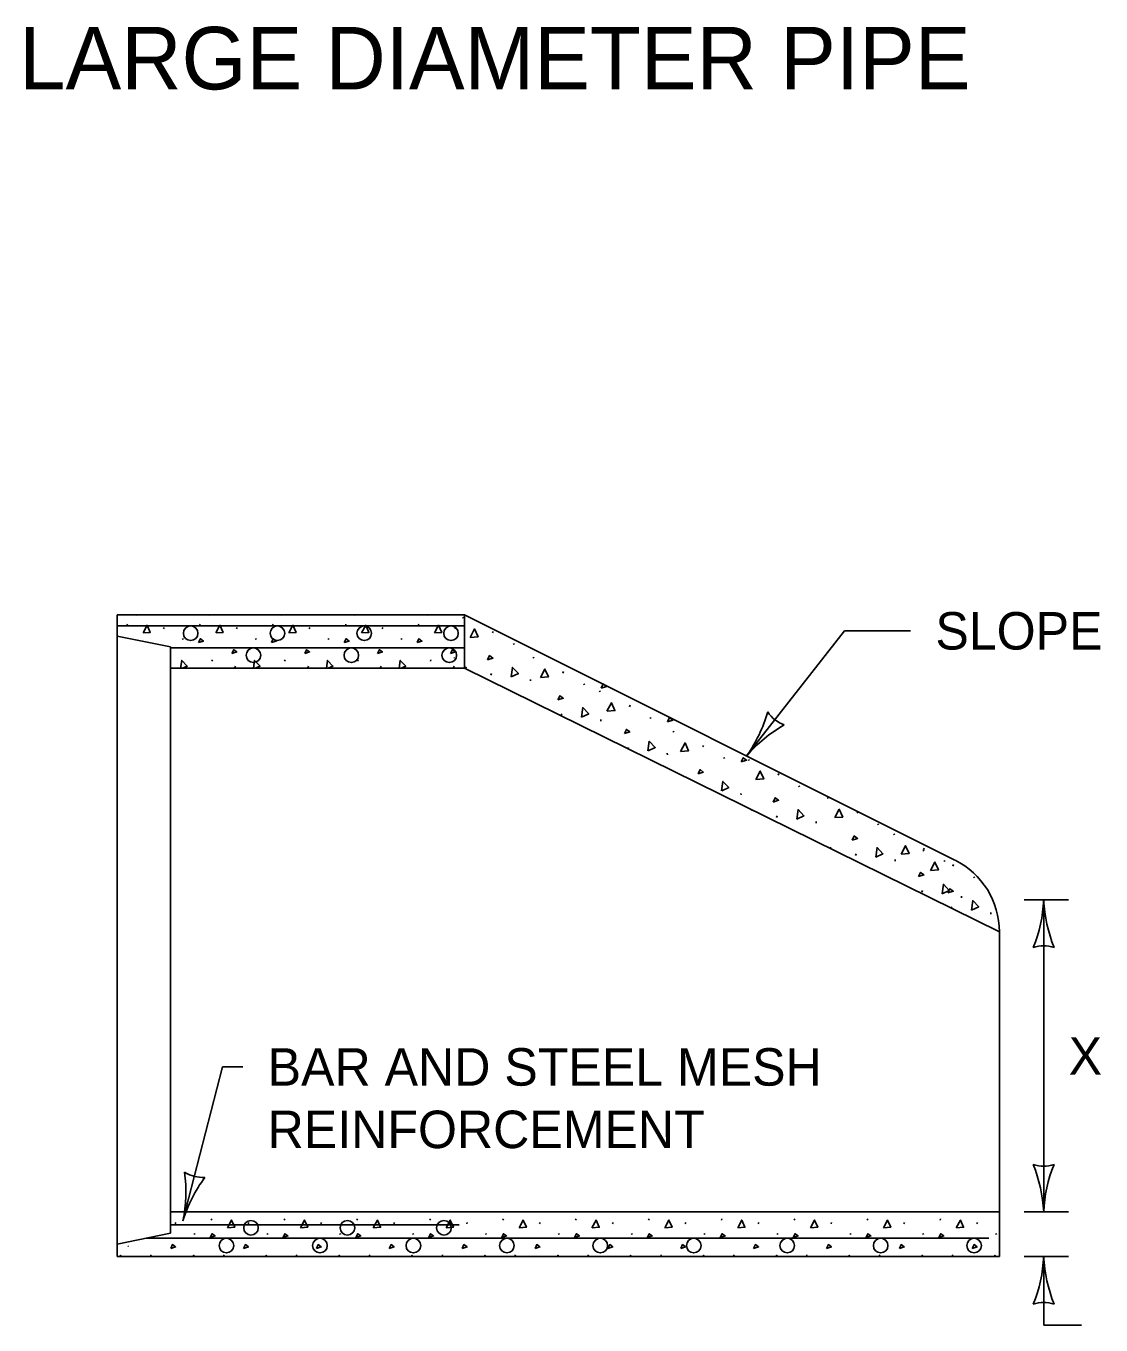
# Model space of a CAD drawing. Extents: x 49991.4 to 50022.1, y 49985 to 50011.4.
# Drawn here: x 50002.773 to 50004.494, y 49990.143 to 49992.222 of the extents above; entities that cross this region are included whole.
import ezdxf

# ---------------------------------------------------------------- set-up
doc = ezdxf.new("R2010")
doc.units = 0
for name, color, linetype in [('Level 1', 7, 'Continuous'), ('Level 2', 7, 'Continuous'), ('Level 3', 7, 'Continuous')]:
    doc.layers.add(name, color=color, linetype=linetype)

msp = doc.modelspace()

# ---------------------------------------------------------------- linework, layer by layer
at = {"layer": 'Level 1'}
for p, q in [((50002.9188, 49991.2797), (50003.4753, 49991.2797)), ((50002.9188, 49990.2549), (50002.9188, 49991.2797)), ((50002.9188, 49991.2797), (50002.9188, 49990.2723)), ((50002.9188, 49991.2797), (50003.4753, 49991.2797)), ((50002.9188, 49991.2797), (50002.9188, 49990.2549)), ((50002.9188, 49990.2549), (50002.9188, 49991.2797)), ((50002.9188, 49990.2549), (50002.9188, 49991.2797)), ((50002.9188, 49990.2549), (50002.9188, 49991.2797)), ((50002.9493, 49991.2797), (50002.9495, 49991.2793)), ((50002.9499, 49991.2797), (50002.9505, 49991.2788)), ((50003.0659, 49991.2797), (50003.0662, 49991.2793)), ((50003.0666, 49991.2797), (50003.0672, 49991.2788)), ((50003.1826, 49991.2797), (50003.1829, 49991.2793)), ((50003.1833, 49991.2797), (50003.1839, 49991.2788)), ((50003.2993, 49991.2797), (50003.2996, 49991.2793)), ((50003.3, 49991.2797), (50003.3006, 49991.2788)), ((50003.416, 49991.2797), (50003.4163, 49991.2793)), ((50003.4167, 49991.2797), (50003.4173, 49991.2788)), ((50003.4723, 49991.276), (50003.4734, 49991.2744)), ((50003.4753, 49991.2797), (50004.2605, 49990.8871)), ((50003.4753, 49991.2797), (50003.4753, 49991.1941)), ((50003.4753, 49991.2797), (50003.4753, 49991.1941)), ((50002.9342, 49991.2627), (50002.9352, 49991.2649)), ((50002.9931, 49991.2571), (50002.9941, 49991.2593)), ((50003.0509, 49991.2627), (50003.0518, 49991.2649)), ((50003.1098, 49991.2571), (50003.1108, 49991.2593)), ((50003.1676, 49991.2627), (50003.1685, 49991.2649)), ((50003.2265, 49991.2571), (50003.2275, 49991.2593)), ((50003.2843, 49991.2627), (50003.2852, 49991.2649)), ((50003.3432, 49991.2571), (50003.3442, 49991.2593)), ((50003.4009, 49991.2627), (50003.4019, 49991.2649)), ((50003.4599, 49991.2571), (50003.4609, 49991.2593)), ((50003.52, 49991.2507), (50003.5211, 49991.2531)), ((50003.0045, 49991.2283), (50002.9188, 49991.2455)), ((50003.0045, 49991.2283), (50002.9188, 49991.2455)), ((50002.9188, 49990.2523), (50002.9188, 49991.2455)), ((50003.0045, 49990.2895), (50003.0045, 49991.2283)), ((50003.0045, 49991.2283), (50003.0045, 49990.2895)), ((50003.0045, 49991.2283), (50003.0045, 49990.2895)), ((50003.0045, 49991.2283), (50003.0045, 49990.2895)), ((50003.0236, 49991.2416), (50003.0246, 49991.2401)), ((50003.1403, 49991.2416), (50003.1413, 49991.2401)), ((50003.257, 49991.2416), (50003.2579, 49991.2401)), ((50003.3737, 49991.2416), (50003.3746, 49991.2401)), ((50003.5533, 49991.2337), (50003.5544, 49991.2321)), ((50003.0704, 49991.2053), (50003.0713, 49991.2074)), ((50003.1871, 49991.2053), (50003.188, 49991.2074)), ((50003.3037, 49991.2053), (50003.3047, 49991.2074)), ((50003.4204, 49991.2053), (50003.4214, 49991.2074)), ((50003.4582, 49991.2115), (50003.4589, 49991.2104)), ((50003.5849, 49991.2117), (50003.586, 49991.2101)), ((50003.4753, 49991.1941), (50003.0045, 49991.1941)), ((50003.4753, 49991.1941), (50003.0045, 49991.1941)), ((50003.1074, 49991.1953), (50003.1084, 49991.1975)), ((50003.2241, 49991.1953), (50003.2251, 49991.1975)), ((50003.3408, 49991.1953), (50003.3417, 49991.1975)), ((50003.4575, 49991.1953), (50003.4584, 49991.1975)), ((50003.4753, 49991.1941), (50004.3315, 49990.7722)), ((50003.4769, 49991.194), (50003.4779, 49991.1964)), ((50003.5174, 49991.1831), (50003.5184, 49991.1855)), ((50003.6326, 49991.1864), (50003.6337, 49991.1888)), ((50003.5807, 49991.1764), (50003.581, 49991.174)), ((50003.6659, 49991.1694), (50003.667, 49991.1678)), ((50003.6914, 49991.1578), (50003.6925, 49991.1562)), ((50003.7391, 49991.1325), (50003.7402, 49991.1349)), ((50003.63, 49991.1188), (50003.631, 49991.1212)), ((50003.6933, 49991.1121), (50003.6936, 49991.1097)), ((50003.7724, 49991.1155), (50003.7735, 49991.1139)), ((50003.8092, 49991.0934), (50003.8103, 49991.0918)), ((50003.7365, 49991.0649), (50003.7375, 49991.0673)), ((50003.8569, 49991.0681), (50003.858, 49991.0705)), ((50003.7998, 49991.0582), (50003.8001, 49991.0558)), ((50003.8902, 49991.0511), (50003.8913, 49991.0495)), ((50003.9296, 49991.0483), (50003.9307, 49991.0467)), ((50003.9773, 49991.023), (50003.9784, 49991.0254)), ((50004.0106, 49991.006), (50004.0117, 49991.0044)), ((50003.9176, 49990.9938), (50003.9179, 49990.9914)), ((50004.0561, 49990.9874), (50004.0572, 49990.9858)), ((50003.9342, 49990.9663), (50003.9352, 49990.9687)), ((50003.9747, 49990.9554), (50003.9757, 49990.9578)), ((50004.1038, 49990.9621), (50004.1049, 49990.9645)), ((50004.038, 49990.9487), (50004.0383, 49990.9463)), ((50004.1371, 49990.9451), (50004.1382, 49990.9435)), ((50004.1623, 49990.9288), (50004.1634, 49990.9272)), ((50004.0607, 49990.9054), (50004.0617, 49990.9078)), ((50004.1012, 49990.8945), (50004.1022, 49990.8969)), ((50004.2094, 49990.9027), (50004.2105, 49990.9011)), ((50004.21, 49990.9035), (50004.2111, 49990.9059)), ((50004.1645, 49990.8878), (50004.1648, 49990.8854)), ((50004.2433, 49990.8865), (50004.2444, 49990.8849)), ((50004.2571, 49990.8774), (50004.2582, 49990.8798)), ((50004.2904, 49990.8604), (50004.2915, 49990.8588)), ((50004.2074, 49990.8359), (50004.2084, 49990.8383)), ((50004.2545, 49990.8098), (50004.2555, 49990.8122)), ((50004.2707, 49990.8292), (50004.271, 49990.8268)), ((50004.3178, 49990.8031), (50004.3181, 49990.8007)), ((50004.3315, 49990.2523), (50004.3315, 49990.7722)), ((50004.3315, 49990.2523), (50004.3315, 49990.7722)), ((50003.0045, 49990.3237), (50004.3315, 49990.3237)), ((50003.0045, 49990.2895), (50003.0045, 49990.3237)), ((50003.0045, 49990.3237), (50004.3315, 49990.3237)), ((50003.0696, 49990.3103), (50003.0705, 49990.3125)), ((50003.1862, 49990.3103), (50003.1872, 49990.3125)), ((50003.3029, 49990.3103), (50003.3039, 49990.3125)), ((50003.4196, 49990.3103), (50003.4206, 49990.3125)), ((50003.5363, 49990.3103), (50003.5373, 49990.3125)), ((50003.653, 49990.3103), (50003.654, 49990.3125)), ((50003.7697, 49990.3103), (50003.7707, 49990.3125)), ((50003.8864, 49990.3103), (50003.8874, 49990.3125)), ((50004.0031, 49990.3103), (50004.004, 49990.3125)), ((50004.1198, 49990.3103), (50004.1207, 49990.3125)), ((50004.2365, 49990.3103), (50004.2374, 49990.3125)), ((50003.0118, 49990.3047), (50003.0128, 49990.3069)), ((50003.1285, 49990.3047), (50003.1295, 49990.3069)), ((50003.2452, 49990.3047), (50003.2462, 49990.3069)), ((50003.3619, 49990.3047), (50003.3629, 49990.3069)), ((50003.4786, 49990.3047), (50003.4796, 49990.3069)), ((50003.5953, 49990.3047), (50003.5962, 49990.3069)), ((50003.712, 49990.3047), (50003.7129, 49990.3069)), ((50003.8286, 49990.3047), (50003.8296, 49990.3069)), ((50003.9453, 49990.3047), (50003.9463, 49990.3069)), ((50004.062, 49990.3047), (50004.063, 49990.3069)), ((50004.1787, 49990.3047), (50004.1797, 49990.3069)), ((50004.2954, 49990.3047), (50004.2964, 49990.3069)), ((50002.9188, 49990.2723), (50003.0045, 49990.2895)), ((50003.0423, 49990.2892), (50003.0432, 49990.2877)), ((50003.159, 49990.2892), (50003.1599, 49990.2877)), ((50003.2757, 49990.2892), (50003.2766, 49990.2877)), ((50003.3923, 49990.2892), (50003.3933, 49990.2877)), ((50003.509, 49990.2892), (50003.51, 49990.2877)), ((50003.6257, 49990.2892), (50003.6267, 49990.2877)), ((50003.7424, 49990.2892), (50003.7434, 49990.2877)), ((50003.8591, 49990.2892), (50003.8601, 49990.2877)), ((50003.9758, 49990.2892), (50003.9768, 49990.2877)), ((50004.0925, 49990.2892), (50004.0935, 49990.2877)), ((50004.2092, 49990.2892), (50004.2101, 49990.2877)), ((50004.3259, 49990.2892), (50004.3268, 49990.2877)), ((50004.3315, 49990.2523), (50002.9188, 49990.2523)), ((50004.3315, 49990.2523), (50002.9188, 49990.2523)), ((50002.9188, 49990.2523), (50004.3315, 49990.2523)), ((50002.9361, 49990.2696), (50002.9368, 49990.2685)), ((50002.9724, 49990.2529), (50002.9733, 49990.255)), ((50003.089, 49990.2529), (50003.09, 49990.255)), ((50003.2057, 49990.2529), (50003.2067, 49990.255)), ((50003.3224, 49990.2529), (50003.3234, 49990.255)), ((50003.4391, 49990.2529), (50003.4401, 49990.255)), ((50003.5558, 49990.2529), (50003.5568, 49990.255)), ((50003.6725, 49990.2529), (50003.6735, 49990.255)), ((50003.7892, 49990.2529), (50003.7902, 49990.255)), ((50003.9059, 49990.2529), (50003.9068, 49990.255)), ((50004.0226, 49990.2529), (50004.0235, 49990.255)), ((50004.1393, 49990.2529), (50004.1402, 49990.255)), ((50004.2559, 49990.2529), (50004.2569, 49990.255))]:
    msp.add_line(p, q, dxfattribs=at)
for points in [[(50002.9195, 49991.2619), (50003.4753, 49991.2619)], [(50002.9603, 49991.2506), (50002.9668, 49991.263), (50002.9719, 49991.2515), (50002.9605, 49991.2506)], [(50003.0769, 49991.2506), (50003.0835, 49991.263), (50003.0886, 49991.2515), (50003.0772, 49991.2506)], [(50003.1936, 49991.2506), (50003.2002, 49991.263), (50003.2053, 49991.2515), (50003.1939, 49991.2506)], [(50003.3103, 49991.2506), (50003.3169, 49991.263), (50003.322, 49991.2515), (50003.3106, 49991.2506)], [(50003.427, 49991.2506), (50003.4336, 49991.263), (50003.4387, 49991.2515), (50003.4273, 49991.2506)], [(50003.4841, 49991.2436), (50003.4913, 49991.2571), (50003.4969, 49991.2446), (50003.4843, 49991.2436)], [(50003.0048, 49991.2267), (50003.4753, 49991.2267)], [(50003.0492, 49991.2352), (50003.0521, 49991.2413), (50003.057, 49991.2377), (50003.0492, 49991.2352)], [(50003.1659, 49991.2352), (50003.1688, 49991.2413), (50003.1737, 49991.2377), (50003.1659, 49991.2352)], [(50003.2825, 49991.2352), (50003.2855, 49991.2413), (50003.2903, 49991.2377), (50003.2825, 49991.2352)], [(50003.3992, 49991.2352), (50003.4022, 49991.2413), (50003.407, 49991.2377), (50003.3992, 49991.2352)], [(50003.0205, 49991.1941), (50003.0223, 49991.2067), (50003.031, 49991.1977), (50003.0234, 49991.1941)], [(50003.1026, 49991.2178), (50003.1055, 49991.2239), (50003.1104, 49991.2202), (50003.1026, 49991.2178)], [(50003.1372, 49991.1941), (50003.139, 49991.2067), (50003.1477, 49991.1977), (50003.1401, 49991.1941)], [(50003.2193, 49991.2178), (50003.2222, 49991.2239), (50003.2271, 49991.2202), (50003.2193, 49991.2178)], [(50003.2539, 49991.1941), (50003.2556, 49991.2067), (50003.2644, 49991.1977), (50003.2567, 49991.1941)], [(50003.3359, 49991.2178), (50003.3389, 49991.2239), (50003.3437, 49991.2202), (50003.3359, 49991.2178)], [(50003.3706, 49991.1941), (50003.3723, 49991.2067), (50003.3811, 49991.1977), (50003.3734, 49991.1941)], [(50003.4526, 49991.2178), (50003.4556, 49991.2239), (50003.4604, 49991.2202), (50003.4526, 49991.2178)], [(50003.5121, 49991.2077), (50003.5153, 49991.2144), (50003.5206, 49991.2104), (50003.5121, 49991.2077)], [(50003.5498, 49991.1803), (50003.5519, 49991.1956), (50003.5614, 49991.1857), (50003.55, 49991.1804)], [(50003.5967, 49991.1793), (50003.6039, 49991.1928), (50003.6095, 49991.1803), (50003.5969, 49991.1793)], [(50003.6939, 49991.1625), (50003.6971, 49991.1691), (50003.7024, 49991.1651), (50003.6939, 49991.1625)], [(50003.6247, 49991.1434), (50003.6279, 49991.1501), (50003.6332, 49991.1461), (50003.6247, 49991.1434)], [(50003.6624, 49991.116), (50003.6645, 49991.1313), (50003.674, 49991.1214), (50003.6626, 49991.1161)], [(50003.7032, 49991.1254), (50003.7104, 49991.1389), (50003.716, 49991.1264), (50003.7034, 49991.1254)], [(50003.8004, 49991.1086), (50003.8036, 49991.1152), (50003.8089, 49991.1112), (50003.8004, 49991.1086)], [(50003.7312, 49991.0895), (50003.7344, 49991.0962), (50003.7397, 49991.0922), (50003.7312, 49991.0895)], [(50003.7689, 49991.0621), (50003.771, 49991.0774), (50003.7805, 49991.0675), (50003.7691, 49991.0622)], [(50003.821, 49991.061), (50003.8282, 49991.0745), (50003.8338, 49991.062), (50003.8212, 49991.061)], [(50003.9182, 49991.0442), (50003.9214, 49991.0508), (50003.9267, 49991.0468), (50003.9182, 49991.0442)], [(50003.849, 49991.0251), (50003.8522, 49991.0318), (50003.8575, 49991.0278), (50003.849, 49991.0251)], [(50003.9414, 49991.0159), (50003.9486, 49991.0294), (50003.9542, 49991.0169), (50003.9416, 49991.0159)], [(50003.8867, 49990.9977), (50003.8888, 49991.013), (50003.8983, 49991.0031), (50003.8869, 49990.9978)], [(50003.9694, 49990.98), (50003.9726, 49990.9867), (50003.9779, 49990.9827), (50003.9694, 49990.98)], [(50004.0071, 49990.9526), (50004.0092, 49990.9679), (50004.0187, 49990.958), (50004.0073, 49990.9527)], [(50004.0679, 49990.955), (50004.0751, 49990.9685), (50004.0807, 49990.956), (50004.0681, 49990.955)], [(50004.0959, 49990.9191), (50004.0991, 49990.9258), (50004.1044, 49990.9218), (50004.0959, 49990.9191)], [(50004.1336, 49990.8917), (50004.1357, 49990.907), (50004.1452, 49990.8971), (50004.1338, 49990.8918)], [(50004.1741, 49990.8964), (50004.1813, 49990.9099), (50004.1869, 49990.8974), (50004.1743, 49990.8964)], [(50004.2212, 49990.8703), (50004.2284, 49990.8838), (50004.234, 49990.8713), (50004.2214, 49990.8703)], [(50004.2021, 49990.8605), (50004.2053, 49990.8672), (50004.2106, 49990.8632), (50004.2021, 49990.8605)], [(50004.2398, 49990.8331), (50004.2419, 49990.8484), (50004.2514, 49990.8385), (50004.24, 49990.8332)], [(50004.2492, 49990.8344), (50004.2524, 49990.8411), (50004.2577, 49990.8371), (50004.2492, 49990.8344)], [(50004.2869, 49990.807), (50004.289, 49990.8223), (50004.2985, 49990.8124), (50004.2871, 49990.8071)], [(50003.0045, 49990.3031), (50003.4665, 49990.3031)], [(50003.0956, 49990.2982), (50003.1022, 49990.3106), (50003.1073, 49990.2991), (50003.0959, 49990.2982)], [(50003.2123, 49990.2982), (50003.2189, 49990.3106), (50003.224, 49990.2991), (50003.2126, 49990.2982)], [(50003.329, 49990.2982), (50003.3356, 49990.3106), (50003.3407, 49990.2991), (50003.3292, 49990.2982)], [(50003.4457, 49990.2982), (50003.4523, 49990.3106), (50003.4574, 49990.2991), (50003.4459, 49990.2982)], [(50003.5624, 49990.2982), (50003.569, 49990.3106), (50003.5741, 49990.2991), (50003.5626, 49990.2982)], [(50003.6791, 49990.2982), (50003.6857, 49990.3106), (50003.6908, 49990.2991), (50003.6793, 49990.2982)], [(50003.7958, 49990.2982), (50003.8023, 49990.3106), (50003.8075, 49990.2991), (50003.796, 49990.2982)], [(50003.9125, 49990.2982), (50003.919, 49990.3106), (50003.9241, 49990.2991), (50003.9127, 49990.2982)], [(50004.0291, 49990.2982), (50004.0357, 49990.3106), (50004.0408, 49990.2991), (50004.0294, 49990.2982)], [(50004.1458, 49990.2982), (50004.1524, 49990.3106), (50004.1575, 49990.2991), (50004.1461, 49990.2982)], [(50004.2625, 49990.2982), (50004.2691, 49990.3106), (50004.2742, 49990.2991), (50004.2628, 49990.2982)], [(50002.9651, 49990.2816), (50004.3146, 49990.2816)], [(50003.0046, 49990.2654), (50003.0075, 49990.2715), (50003.0124, 49990.2678), (50003.0046, 49990.2654)], [(50003.0679, 49990.2828), (50003.0708, 49990.2889), (50003.0756, 49990.2853), (50003.0679, 49990.2828)], [(50003.1213, 49990.2654), (50003.1242, 49990.2715), (50003.129, 49990.2678), (50003.1213, 49990.2654)], [(50003.1845, 49990.2828), (50003.1875, 49990.2889), (50003.1923, 49990.2853), (50003.1845, 49990.2828)], [(50003.2379, 49990.2654), (50003.2409, 49990.2715), (50003.2457, 49990.2678), (50003.2379, 49990.2654)], [(50003.3012, 49990.2828), (50003.3042, 49990.2889), (50003.309, 49990.2853), (50003.3012, 49990.2828)], [(50003.3546, 49990.2654), (50003.3576, 49990.2715), (50003.3624, 49990.2678), (50003.3546, 49990.2654)], [(50003.4179, 49990.2828), (50003.4208, 49990.2889), (50003.4257, 49990.2853), (50003.4179, 49990.2828)], [(50003.4713, 49990.2654), (50003.4742, 49990.2715), (50003.4791, 49990.2678), (50003.4713, 49990.2654)], [(50003.5346, 49990.2828), (50003.5375, 49990.2889), (50003.5424, 49990.2853), (50003.5346, 49990.2828)], [(50003.588, 49990.2654), (50003.5909, 49990.2715), (50003.5958, 49990.2678), (50003.588, 49990.2654)], [(50003.6513, 49990.2828), (50003.6542, 49990.2889), (50003.6591, 49990.2853), (50003.6513, 49990.2828)], [(50003.7047, 49990.2654), (50003.7076, 49990.2715), (50003.7125, 49990.2678), (50003.7047, 49990.2654)], [(50003.768, 49990.2828), (50003.7709, 49990.2889), (50003.7758, 49990.2853), (50003.768, 49990.2828)], [(50003.8214, 49990.2654), (50003.8243, 49990.2715), (50003.8292, 49990.2678), (50003.8214, 49990.2654)], [(50003.8847, 49990.2828), (50003.8876, 49990.2889), (50003.8925, 49990.2853), (50003.8847, 49990.2828)], [(50003.9381, 49990.2654), (50003.941, 49990.2715), (50003.9459, 49990.2678), (50003.9381, 49990.2654)], [(50004.0014, 49990.2828), (50004.0043, 49990.2889), (50004.0092, 49990.2853), (50004.0014, 49990.2828)], [(50004.0548, 49990.2654), (50004.0577, 49990.2715), (50004.0626, 49990.2678), (50004.0548, 49990.2654)], [(50004.1181, 49990.2828), (50004.121, 49990.2889), (50004.1259, 49990.2853), (50004.1181, 49990.2828)], [(50004.1715, 49990.2654), (50004.1744, 49990.2715), (50004.1793, 49990.2678), (50004.1715, 49990.2654)], [(50004.2347, 49990.2828), (50004.2377, 49990.2889), (50004.2425, 49990.2853), (50004.2347, 49990.2828)], [(50004.2881, 49990.2654), (50004.2911, 49990.2715), (50004.2959, 49990.2678), (50004.2881, 49990.2654)], [(50002.924, 49990.2523), (50002.9243, 49990.2543), (50002.9262, 49990.2523)], [(50003.0407, 49990.2523), (50003.041, 49990.2543), (50003.0429, 49990.2523)], [(50003.1573, 49990.2523), (50003.1576, 49990.2543), (50003.1596, 49990.2523)], [(50003.274, 49990.2523), (50003.2743, 49990.2543), (50003.2763, 49990.2523)], [(50003.3907, 49990.2523), (50003.391, 49990.2543), (50003.3929, 49990.2523)], [(50003.5074, 49990.2523), (50003.5077, 49990.2543), (50003.5096, 49990.2523)], [(50003.6241, 49990.2523), (50003.6244, 49990.2543), (50003.6263, 49990.2523)], [(50003.7408, 49990.2523), (50003.7411, 49990.2543), (50003.743, 49990.2523)], [(50003.8575, 49990.2523), (50003.8578, 49990.2543), (50003.8597, 49990.2523)], [(50003.9742, 49990.2523), (50003.9745, 49990.2543), (50003.9764, 49990.2523)], [(50004.0909, 49990.2523), (50004.0912, 49990.2543), (50004.0931, 49990.2523)], [(50004.2075, 49990.2523), (50004.2078, 49990.2543), (50004.2098, 49990.2523)], [(50004.3242, 49990.2523), (50004.3245, 49990.2543), (50004.3265, 49990.2523)]]:
    msp.add_lwpolyline(points, dxfattribs=at)
for centre in [(50003.0366, 49991.2502), (50003.1756, 49991.2502), (50003.3145, 49991.2502), (50003.4535, 49991.2502), (50003.1371, 49991.215), (50003.2939, 49991.215), (50003.4507, 49991.215), (50003.1332, 49990.2983), (50003.2877, 49990.2983), (50003.4422, 49990.2983), (50003.0939, 49990.2699), (50003.2436, 49990.2699), (50003.3932, 49990.2699), (50003.5429, 49990.2699), (50003.6925, 49990.2699), (50003.8422, 49990.2699), (50003.9918, 49990.2699), (50004.1415, 49990.2699), (50004.2911, 49990.2699)]:
    msp.add_circle(centre, 0.0117, dxfattribs=at)
msp.add_arc((50004.2031, 49990.7722), 0.1284, 0, 63.435, dxfattribs=at)
at = {"layer": 'Level 3'}
for p, q in [((50004.0838, 49991.2541), (50003.9269, 49991.0539)), ((50004.1891, 49991.2541), (50004.0838, 49991.2541)), ((50004.3715, 49990.8232), (50004.4425, 49990.8232)), ((50004.4025, 49990.3237), (50004.4025, 49990.8232)), ((50003.0873, 49990.5559), (50003.0243, 49990.3095)), ((50003.1199, 49990.5559), (50003.0873, 49990.5559)), ((50004.3715, 49990.3237), (50004.4425, 49990.3237)), ((50004.3715, 49990.2523), (50004.4425, 49990.2523)), ((50004.4025, 49990.1427), (50004.4025, 49990.2523)), ((50004.4025, 49990.1427), (50004.4632, 49990.1427))]:
    msp.add_line(p, q, dxfattribs=at)
for centre, radius, start, end in [((50003.7366, 49991.1884), 0.233, 324.7403, 343.9902), ((50004.006, 49991.1548), 0.0548, 214.0518, 249.7742), ((50004.0961, 49990.9097), 0.2223, 119.369, 139.5525), ((50004.1804, 49990.8324), 0.2223, 337.456, 357.6395), ((50004.6352, 49990.8347), 0.233, 182.8273, 202.0772), ((50004.4025, 49990.695), 0.0548, 72.1388, 107.8612), ((50004.4025, 49990.4519), 0.0548, 252.1388, 287.8612), ((50004.1698, 49990.3122), 0.233, 2.8273, 22.0772), ((50004.6246, 49990.3145), 0.2223, 157.456, 177.6395), ((50002.796, 49990.356), 0.233, 348.4851, 7.7349), ((50003.2372, 49990.2456), 0.2223, 143.1138, 163.2973), ((50003.0561, 49990.4337), 0.0548, 237.7966, 273.519), ((50004.1804, 49990.2615), 0.2223, 337.456, 357.6395), ((50004.6352, 49990.2638), 0.233, 182.8273, 202.0772), ((50004.4025, 49990.1241), 0.0548, 72.1388, 107.8612)]:
    msp.add_arc(centre, radius, start, end, dxfattribs=at)

# ---------------------------------------------------------------- texts
at = {"layer": 'Level 2'}
for s, height, p in [('LARGE DIAMETER PIPE', 0.1, (50002.7619, 49992.1209)), ('SLOPE', 0.06, (50004.2291, 49991.2241)), ('X', 0.06, (50004.4425, 49990.5434)), ('BAR AND STEEL MESH', 0.06, (50003.1599, 49990.5259)), ('REINFORCEMENT', 0.06, (50003.1599, 49990.4259))]:
    msp.add_text(s, height=height, dxfattribs=at).set_placement(p)

doc.saveas('drawing.dxf')
